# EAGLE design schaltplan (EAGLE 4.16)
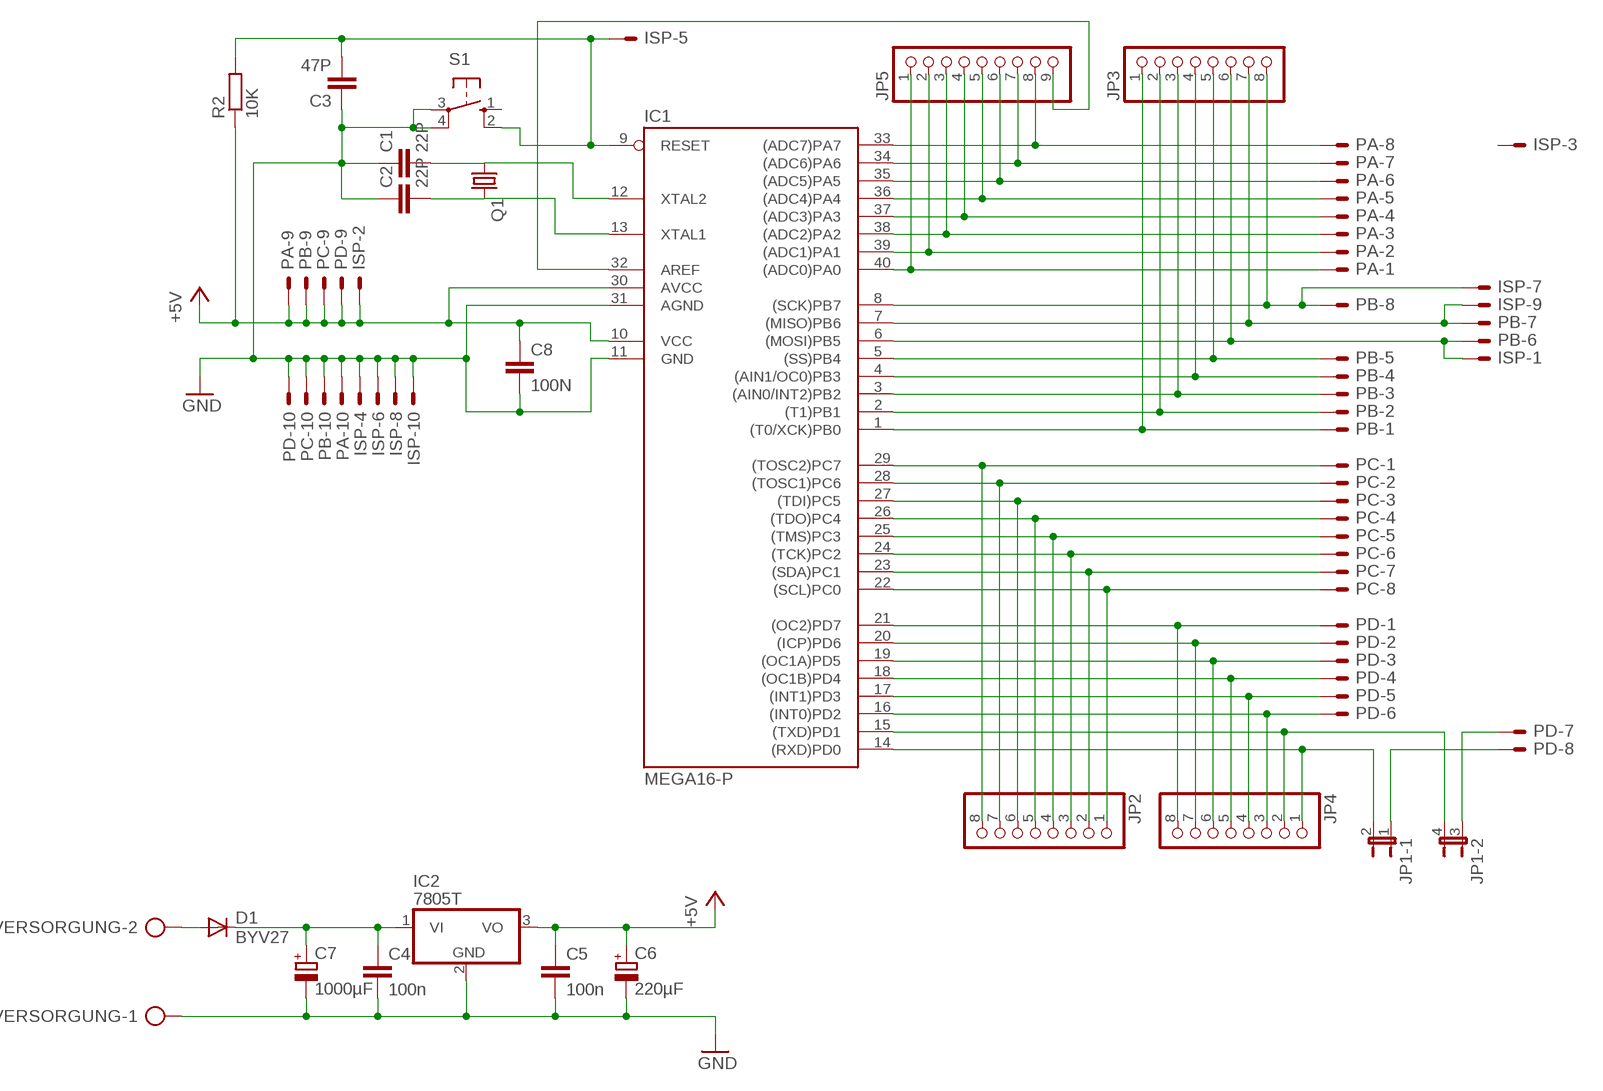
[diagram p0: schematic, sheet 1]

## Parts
C1  22P  C-EU025-024X044  [C025-024X044]
C2  22P  C-EU025-024X044  [C025-024X044]
C3  47P  C-EU025-024X044  [C025-024X044]
C4  100n  C-EU050-024X044  [C050-024X044]
C5  100n  C-EU050-024X044  [C050-024X044]
C6  220µF  CPOL-EUE5-10.5  [E5-10,5]
C7  1000µF  CPOL-EUE5-13  [E5-13]
C8  100N  C-EU050-024X044  [C050-024X044]
D1  BYV27  [SOD57-10]
IC1  MEGA16-P  [DIL40]
IC2  7805T  [TO220H]
ISP  ML10E  [ML10]
JP1  JP2QE  [JP2Q]
JP2  PINHD-1X8  [1X08]
JP3  PINHD-1X8  [1X08]
JP4  PINHD-1X8  [1X08]
JP5  PINHD-1X9  [1X09]
PA  ML10E  [ML10]
PB  ML10E  [ML10]
PC  ML10E  [ML10]
PD  ML10E  [ML10]
Q1  CRYSTALHC18U-V  [HC18U-V]
R2  10K  R-EU_0207/7  [0207/7]
S1  10-XX  [B3F-10XX]
VERSORGUNG  AK500/2  [AK500/2]

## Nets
+5V: C5.1 C6.+ C8.1 IC1.10(VCC) IC1.30(AVCC) IC2.3(VO) ISP.2 PA.9 PB.9 PC.9 PD.9 R2.1
GND: C1.1 C2.1 C3.1 C4.2 C5.2 C6.- C7.- C8.2 IC1.11(GND) IC1.31(AGND) IC2.2(GND) ISP.4 ISP.6 ISP.8 ISP.10 PA.10 PB.10 PC.10 PD.10 S1.3(P) S1.4(P1) VERSORGUNG.1
N$1: IC1.33((ADC7)PA7) JP5.8 PA.8
N$2: IC1.34((ADC6)PA6) JP5.7 PA.7
N$3: IC1.35((ADC5)PA5) JP5.6 PA.6
N$4: IC1.36((ADC4)PA4) JP5.5 PA.5
N$5: IC1.37((ADC3)PA3) JP5.4 PA.4
N$6: IC1.38((ADC2)PA2) JP5.3 PA.3
N$7: IC1.39((ADC1)PA1) JP5.2 PA.2
N$8: IC1.40((ADC0)PA0) JP5.1 PA.1
N$9: IC1.6((MOSI)PB5) ISP.1 JP3.6 PB.6
N$10: D1.A VERSORGUNG.2
N$12: JP1.1 PD.8
N$13: JP1.3 PD.7
N$14: C4.1 C7.+ D1.C IC2.1(VI)
N$15: IC1.2((T1)PB1) JP3.2 PB.2
N$16: IC1.1((T0/XCK)PB0) JP3.1 PB.1
N$17: IC1.29((TOSC2)PC7) JP2.8 PC.1
N$18: IC1.28((TOSC1)PC6) JP2.7 PC.2
N$19: IC1.27((TDI)PC5) JP2.6 PC.3
N$20: IC1.26((TDO)PC4) JP2.5 PC.4
N$21: IC1.25((TMS)PC3) JP2.4 PC.5
N$22: IC1.24((TCK)PC2) JP2.3 PC.6
N$23: IC1.23((SDA)PC1) JP2.2 PC.7
N$24: IC1.22((SCL)PC0) JP2.1 PC.8
N$25: IC1.21((OC2)PD7) JP4.8 PD.1
N$26: IC1.20((ICP)PD6) JP4.7 PD.2
N$27: IC1.19((OC1A)PD5) JP4.6 PD.3
N$28: IC1.18((OC1B)PD4) JP4.5 PD.4
N$29: IC1.17((INT1)PD3) JP4.4 PD.5
N$30: IC1.16((INT0)PD2) JP4.3 PD.6
N$31: IC1.15((TXD)PD1) JP1.4 JP4.2
N$32: IC1.14((RXD)PD0) JP1.2 JP4.1
N$33: C1.2 IC1.12(XTAL2) Q1.1
N$36: C2.2 IC1.13(XTAL1) Q1.2
N$37: C3.2 IC1.9(RESET) ISP.5 R2.2 S1.2(S1)
N$40: IC1.7((MISO)PB6) ISP.9 JP3.7 PB.7
N$41: IC1.8((SCK)PB7) ISP.7 JP3.8 PB.8
N$42: IC1.32(AREF) JP5.9
N$44: IC1.3((AIN0/INT2)PB2) JP3.3 PB.3
N$46: IC1.4((AIN1/OC0)PB3) JP3.4 PB.4
N$47: IC1.5((SS)PB4) JP3.5 PB.5
Unconnected: ISP.3 S1.1(S)

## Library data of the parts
C1-C5 C8 = rcl:C-EU: CAPACITOR, European symbol
C6 C7 = rcl:CPOL-EU: POLARIZED CAPACITOR, European symbol
D1 = diode:BYV27: DIODE
IC1 = atmel:MEGA16-P: MICROCONTROLLER 16 Kbytes FLASH 1 kbytes SRAM 512 bytes EEPROM USART 8-channel 10 bit ADC Source: avr.lbr
IC2 = linear:78*: Positive VOLTAGE REGULATOR Source: http://cache.national.com/ds/LM/LM78L05.pdf http://www.fairchildsemi.com/ds/LM/LM7805.pdf
ISP PA PB PC PD = con-harting-ml:ML10?E: HARTING
JP1 = jumper:JP2QE: JUMPER
JP2-JP4 = pinhead:PINHD-1X8: PIN HEADER
JP5 = pinhead:PINHD-1X9: PIN HEADER
Q1 = crystal:CRYSTAL: CRYSTAL
R2 = rcl:R-EU_: RESISTOR, European symbol
S1 = switch-omron:10-XX: OMRON SWITCH
VERSORGUNG = con-ptr500:AK500/2: CONNECTOR

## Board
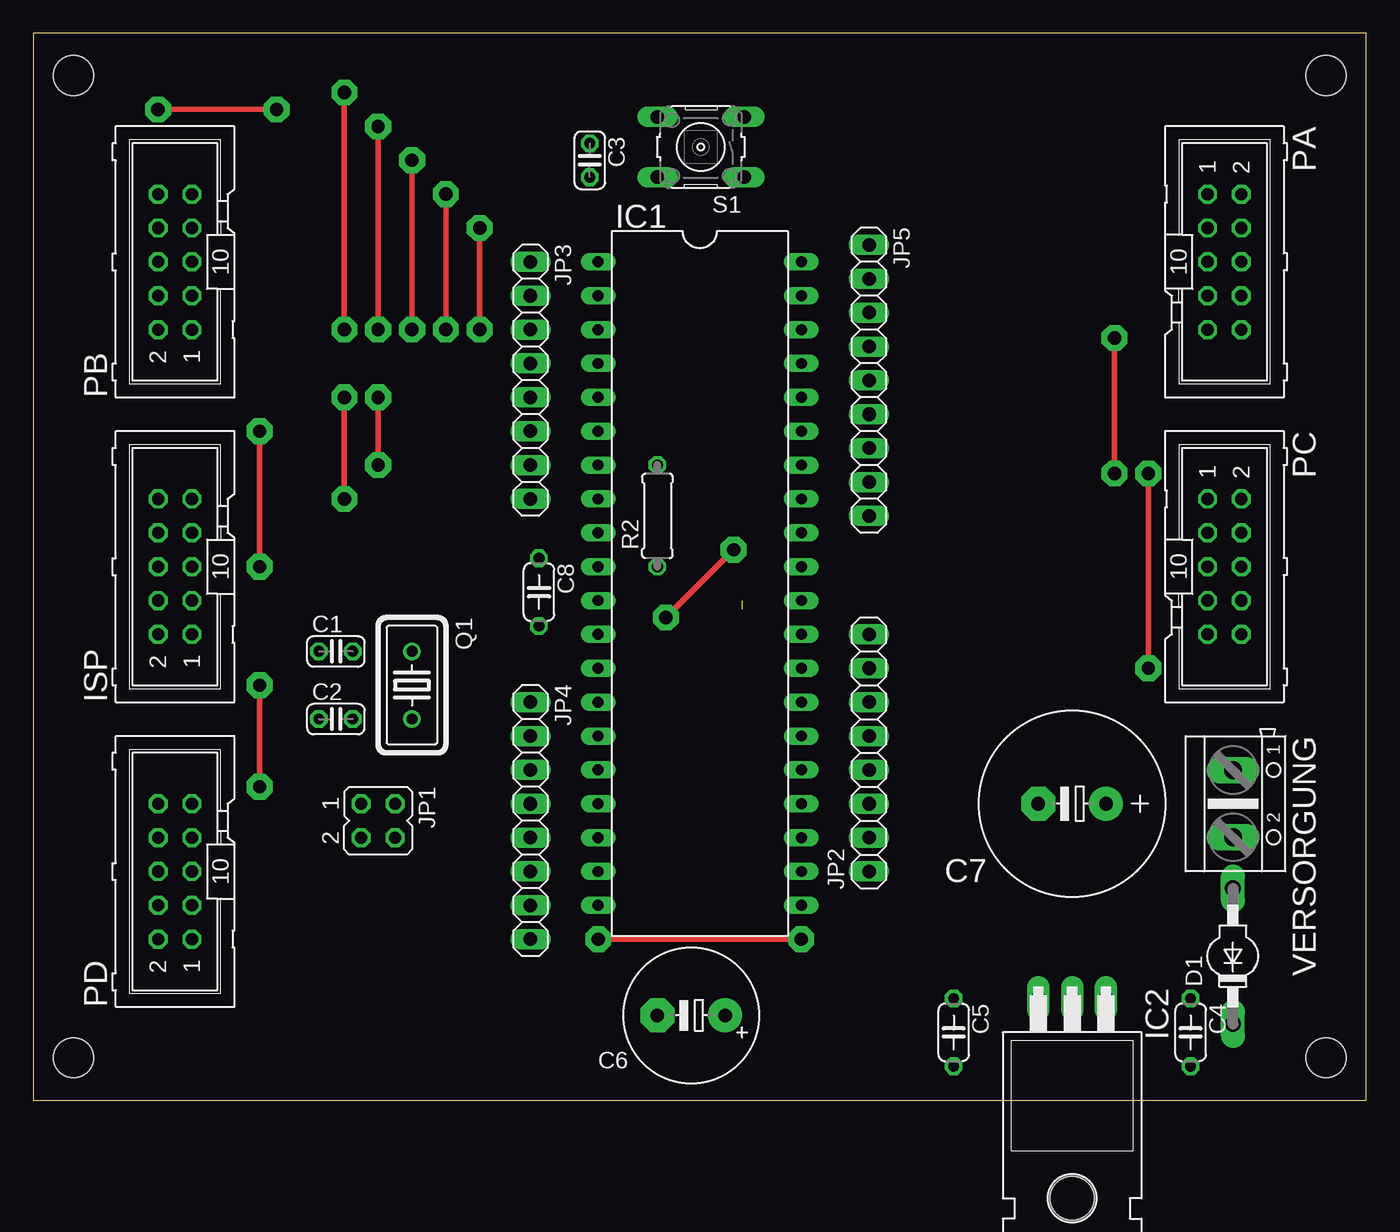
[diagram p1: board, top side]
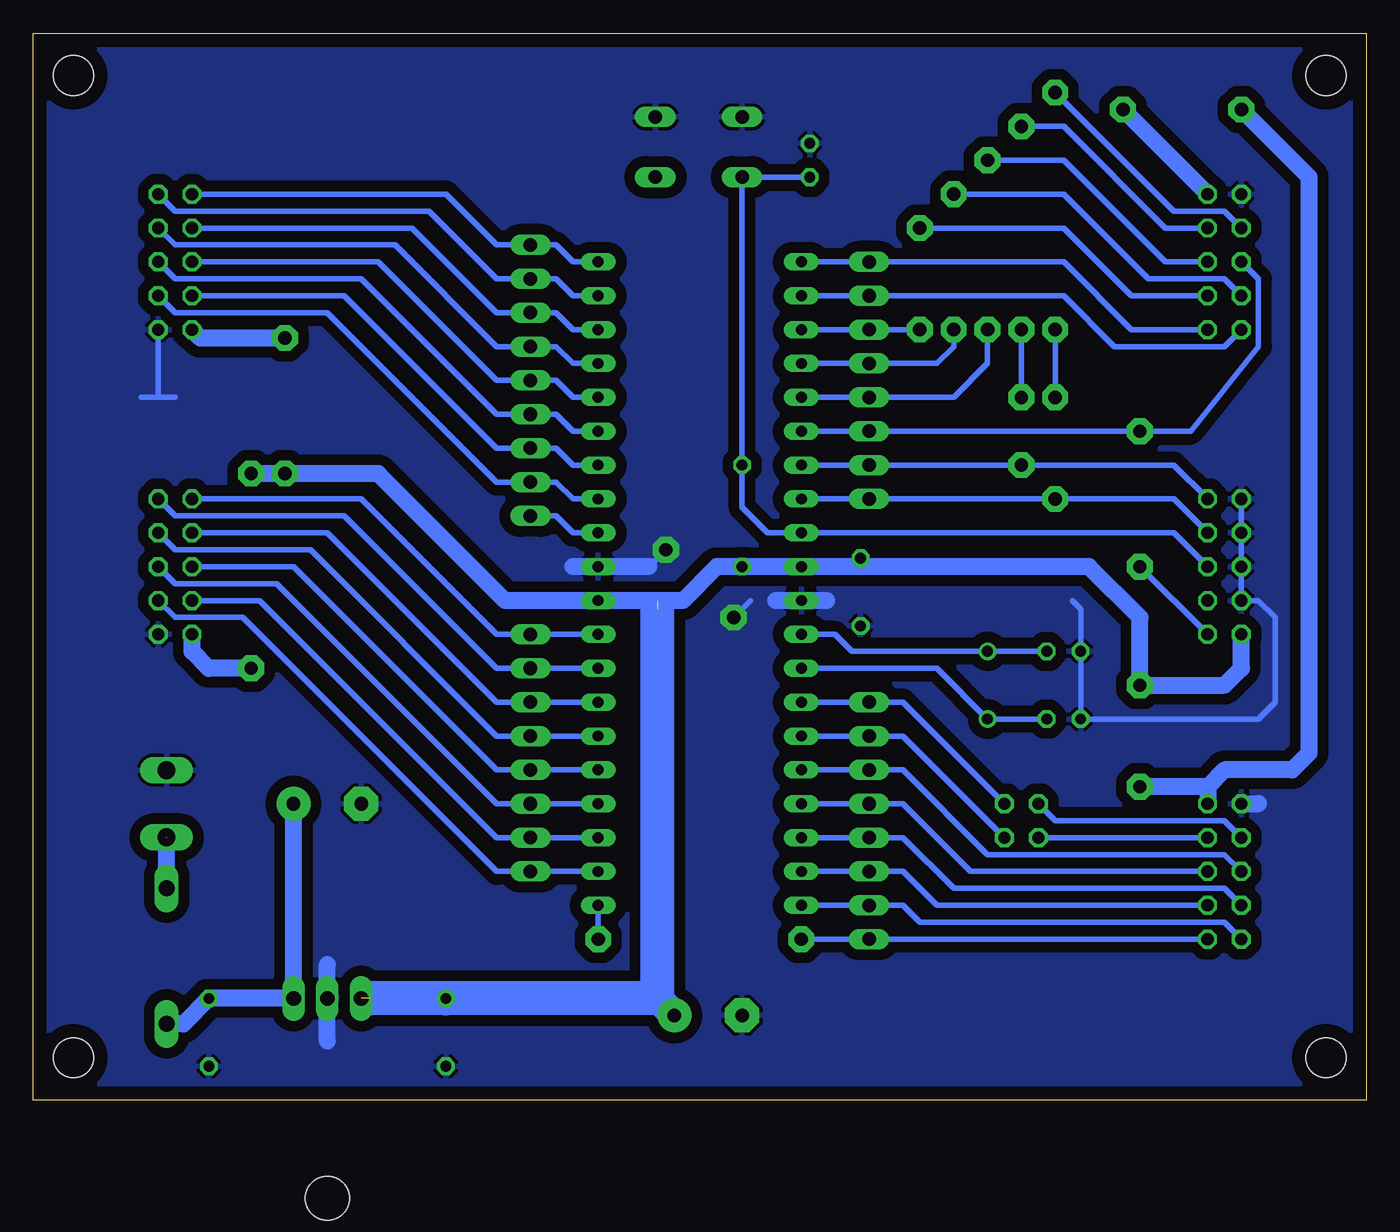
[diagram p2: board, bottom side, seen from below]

Size 100 x 80 mm. Coordinates in mm from the lower left corner, seen from the top.
Outline: 0,0 100,0 100,80 0,80 0,0
Copper layers (1*16): Top 0.035mm / dielectric 1.5mm / Bottom 0.035mm
Design rules "default": minimum track width 10mil, minimum drill 24mil, track to track 8mil, track to pad 8mil, pad to pad 8mil, via to via 8mil, smd to smd 8mil, copper to edge 40mil, drill to drill 8mil, minimum pad ring 10mil, minimum via ring 8mil, stop-mask expansion 4mil, vias tented up to drill 0mil, thermal gap 10mil
Holes 3 mm at 3.01,3.17 96.99,3.17 3.01,76.83 96.99,76.83

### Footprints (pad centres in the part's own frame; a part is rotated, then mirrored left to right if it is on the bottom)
C025-024X044 = drill 0.813 octagon: 1 -1.27,0; 2 1.27,0
C050-024X044 = drill 0.813 octagon: 1 -2.54,0; 2 2.54,0
E5-10,5 = drill 1.016 pad 2.54 round: + -2.54,0 | drill 1.016 pad 2.54 octagon: - 2.54,0
E5-13 = drill 1.016 pad 2.54 round: + -2.54,0 | drill 1.016 pad 2.54 octagon: - 2.54,0
SOD57-10 = drill 1.194 long: A 5.08,0; C -5.08,0
DIL40 = drill 0.813 long: 1 -24.13,-7.62; 2 -21.59,-7.62; 3 -19.05,-7.62; 4 -16.51,-7.62; 5 -13.97,-7.62; 6 -11.43,-7.62; 7 -8.89,-7.62; 8 -6.35,-7.62; 9 -3.81,-7.62; 10 -1.27,-7.62; 11 1.27,-7.62; 12 3.81,-7.62; 13 6.35,-7.62; 14 8.89,-7.62; 15 11.43,-7.62; 16 13.97,-7.62; 17 16.51,-7.62; 18 19.05,-7.62; 19 21.59,-7.62; 20 24.13,-7.62; 21 24.13,7.62; 22 21.59,7.62; 23 19.05,7.62; 24 16.51,7.62; 25 13.97,7.62; 26 11.43,7.62; 27 8.89,7.62; 28 6.35,7.62; 29 3.81,7.62; 30 1.27,7.62; 31 -1.27,7.62; 32 -3.81,7.62; 33 -6.35,7.62; 34 -8.89,7.62; 35 -11.43,7.62; 36 -13.97,7.62; 37 -16.51,7.62; 38 -19.05,7.62; 39 -21.59,7.62; 40 -24.13,7.62
TO220H = drill 1.118 long: 1 -2.54,-10.16; 2 0,-10.16; 3 2.54,-10.16 | hole 3.302: 0,4.826
ML10 = drill 0.914 octagon: 1 -5.08,-1.27; 2 -5.08,1.27; 3 -2.54,-1.27; 4 -2.54,1.27; 5 0,-1.27; 6 0,1.27; 7 2.54,-1.27; 8 2.54,1.27; 9 5.08,-1.27; 10 5.08,1.27
JP2Q = drill 0.914 octagon: 1 -1.27,-1.27; 2 -1.27,1.27; 3 1.27,-1.27; 4 1.27,1.27
1X08 = drill 1.016 long: 1 -8.89,0; 2 -6.35,0; 3 -3.81,0; 4 -1.27,0; 5 1.27,0; 6 3.81,0; 7 6.35,0; 8 8.89,0
1X09 = drill 1.016 long: 1 -10.16,0; 2 -7.62,0; 3 -5.08,0; 4 -2.54,0; 5 0,0; 6 2.54,0; 7 5.08,0; 8 7.62,0; 9 10.16,0
HC18U-V = drill 0.813 round: 1 -2.54,0; 2 2.54,0
0207/7 = drill 0.813 octagon: 1 -3.81,0; 2 3.81,0
B3F-10XX = drill 1.016 long: 1 -3.251,2.261; 2 3.251,2.261; 3 -3.251,-2.261; 4 3.251,-2.261
AK500/2 = drill 1.321 long: 1 -2.515,0; 2 2.515,0

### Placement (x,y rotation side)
C1  22.7,33.65 0 top
C2  22.7,28.57 0 top
C3  41.74,70.48 270 top
C4  86.83,5.08 270 top
C5  69.05,5.08 270 top
C6  49.37,6.34 180 top
C7  77.94,22.22 180 top
C8  37.94,38.1 270 top
D1  90,10.79 90 top
IC1  50,38.73 270 top
IC2  77.94,-2.54 180 top
ISP  10.63,40 90 top
JP1  25.87,20.95 270 top
JP2  62.7,26.03 90 top
JP3  37.3,53.97 270 top
JP4  37.3,20.95 270 top
JP5  62.7,53.97 270 top
PA  89.37,62.86 270 top
PB  10.63,62.86 90 top
PC  89.37,40 270 top
PD  10.63,17.14 90 top
Q1  28.41,31.11 270 top
R2  46.82,43.81 90 top
S1  50.08,71.47 180 top
VERSORGUNG  90,22.22 270 top

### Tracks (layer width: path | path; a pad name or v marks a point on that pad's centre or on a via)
+5V  (via drill 1 pad 1.93)  (2 unrouted)
  Top 0.406: v16.98,23.49 v16.98,31.11 | v9.36,74.29 v18.25,74.29 | v81.11,46.98 v81.11,57.15 | v83.66,46.98 v83.66,32.38
  Bottom 1.27: ISP.2 9.36,32.38 10.63,31.11 v16.98,31.11 16.98,36.19 20.79,40 37.94,40 | 11.9,23.49 PD.9 | 11.9,23.49 v16.98,23.49 | 11.9,23.49 10.63,24.76 5.55,24.76 4.28,26.03 4.28,69.21 v9.36,74.29 | v18.25,74.29 PB.9 | v83.66,46.98 v81.11,46.98 74.13,46.98 64.61,37.46 IC1.30 53.17,37.46 51.27,37.46 48.73,40 R2.1 IC1.10 37.94,40 | v83.66,32.38 86.83,32.38 88.1,33.65 PC.9 | v81.11,57.15 87.47,57.15 PA.9 | 37.94,40 C8.1
  Bottom 2.184: C6.+ 53.17,7.62
  Bottom 2.54: 74.77,7.62 C5.1 53.17,7.62 53.17,36.83
GND  (via drill 1 pad 1.93)
  Top 0.406: v47.46,36.19 v52.54,41.27
  Bottom 0.406: 22.06,37.46 21.42,36.83 C2.1 8.09,28.57 6.82,29.84 6.82,36.19 8.09,37.46 ISP.4 ISP.10 | v47.46,36.19 46.19,37.46 | v52.54,41.27 53.81,40 | 90.64,52.7 89.37,52.7 | 90.64,52.7 PA.10 | 90.64,52.7 91.91,52.7
  Bottom 1.27: 53.81,40 IC1.31 59.52,40 | PD.10 8.09,22.22 | 77.94,10.16 IC2.2 77.94,4.44 | 44.28,37.46 IC1.11 40.48,37.46
  pour Bottom (isolate 0.813): 0.47,0.63 0.47,79.37 99.53,79.37 99.53,0.63
N$1
  Bottom 0.406: IC1.33 59.52,45.08 60.8,46.35 JP5.8 65.24,46.35 77.94,59.05 89.37,59.05 PA.8
N$2
  Bottom 0.406: IC1.34 59.52,47.62 60.8,48.89 JP5.7 65.24,48.89 76.67,60.32 PA.7
N$3
  Bottom 0.406: IC1.35 59.52,50.16 60.8,51.43 JP5.6 65.24,51.43 75.4,61.59 89.37,61.59 PA.6
N$4
  Bottom 0.406: IC1.36 59.52,52.7 60.8,53.97 JP5.5 65.24,53.97 74.13,62.86 PA.5
N$5
  Bottom 0.406: IC1.37 59.52,55.24 60.8,56.51 JP5.4 65.24,56.51 72.86,64.13 89.37,64.13 PA.4
N$6
  Bottom 0.406: IC1.38 59.52,57.78 60.8,59.05 JP5.3 65.24,59.05 71.59,65.4 PA.3
N$7
  Bottom 0.406: IC1.39 59.52,60.32 60.8,61.59 JP5.2 65.24,61.59 70.32,66.67 89.37,66.67 PA.2
N$8
  Bottom 0.406: IC1.40 59.52,62.86 60.8,64.13 JP5.1 65.24,64.13 69.05,67.94 PA.1
N$9  (via drill 1 pad 1.93)
  Top 0.406: v16.98,40 v16.98,50.16
  Bottom 0.406: ISP.1 v16.98,40 | PB.6 8.09,61.59 8.09,56.51 13.17,50.16 v16.98,50.16 JP3.6 IC1.6
N$10  (1 unrouted)
  Bottom 1.27: D1.A 90,19.68
N$12
  Bottom 0.406: JP1.1 23.33,20.95 10.63,20.95 PD.8
N$13
  Bottom 0.406: PD.7 JP1.3
N$14
  Bottom 1.27: C7.+ IC2.1 C4.1 88.73,5.71 D1.C
N$15
  Bottom 0.406: PB.2 10.63,56.51 18.88,56.51 22.7,60.32 JP3.2 IC1.2
N$16
  Bottom 0.406: PB.1 17.61,57.78 22.7,62.86 JP3.1 IC1.1
N$17
  Bottom 0.406: IC1.29 JP2.8 65.24,34.92 75.4,45.08 PC.1
N$18
  Bottom 0.406: IC1.28 JP2.7 65.24,32.38 76.67,43.81 89.37,43.81 PC.2
N$19
  Bottom 0.406: IC1.27 JP2.6 65.24,29.84 77.94,42.54 PC.3
N$20
  Bottom 0.406: IC1.26 JP2.5 65.24,27.3 79.21,41.27 89.37,41.27 PC.4
N$21
  Bottom 0.406: IC1.25 JP2.4 65.24,24.76 80.48,40 PC.5
N$22
  Bottom 0.406: IC1.24 JP2.3 65.24,22.22 81.75,38.73 89.37,38.73 PC.6
N$23
  Bottom 0.406: IC1.23 JP2.2 65.24,19.68 83.02,37.46 PC.7
N$24
  Bottom 0.406: IC1.22 JP2.1 65.24,17.14 84.29,36.19 89.37,36.19 PC.8
N$25  (via drill 1 pad 1.93)
  Top 0.406: v42.38,12.06 v57.62,12.06
  Bottom 0.406: PD.1 JP4.8 v42.38,12.06 43.02,12.06 | v57.62,12.06 IC1.21
N$26
  Bottom 0.406: IC1.20 JP4.7 34.76,14.6 33.49,13.33 10.63,13.33 PD.2
N$27
  Bottom 0.406: IC1.19 JP4.6 34.76,17.14 32.22,14.6 PD.3
N$28
  Bottom 0.406: IC1.18 JP4.5 34.76,19.68 30.95,15.87 10.63,15.87 PD.4
N$29
  Bottom 0.406: IC1.17 JP4.4 34.76,22.22 29.68,17.14 PD.5
N$30
  Bottom 0.406: IC1.16 JP4.3 34.76,24.76 28.41,18.41 10.63,18.41 PD.6
N$31
  Bottom 0.406: JP1.4 34.76,27.3 JP4.2 IC1.15
N$32
  Bottom 0.406: JP1.2 34.76,29.84 JP4.1 IC1.14
N$33
  Bottom 0.406: IC1.12 39.84,34.92 38.57,33.65 Q1.1 C1.2
N$36
  Bottom 0.406: C2.2 Q1.2 32.22,32.38 IC1.13
N$37  (1 unrouted)
  Bottom 0.406: ISP.5 14.44,42.54 IC1.9 44.92,42.54 46.82,44.45 R2.2 S1.2 C3.2
N$40  (via drill 1 pad 1.93)
  Top 0.406: v25.87,57.78 v25.87,73.02 | v25.87,47.62 v25.87,52.7
  Bottom 0.406: v25.87,73.02 22.7,73.02 15.08,65.4 PB.7 | ISP.9 14.44,47.62 v25.87,47.62 JP3.7 IC1.7 | v25.87,52.7 v25.87,57.78
N$41  (via drill 1 pad 1.93)
  Top 0.406: v23.33,57.78 v23.33,75.56 | v23.33,45.08 v23.33,52.7
  Bottom 0.406: v23.33,75.56 14.44,66.67 10.63,66.67 PB.8 | ISP.7 14.44,45.08 v23.33,45.08 JP3.8 IC1.8 | v23.33,52.7 v23.33,57.78
N$42
  Bottom 0.406: IC1.32 59.52,42.54 60.8,43.81 JP5.9
N$44  (via drill 1 pad 1.93)
  Top 0.406: v33.49,65.4 v33.49,57.78
  Bottom 0.406: v33.49,65.4 22.7,65.4 17.61,60.32 PB.3 | IC1.3 JP3.3 v33.49,57.78
N$46  (via drill 1 pad 1.93)
  Top 0.406: v30.95,67.94 v30.95,57.78
  Bottom 0.406: v30.95,67.94 22.7,67.94 16.34,61.59 10.63,61.59 PB.4 | v30.95,57.78 30.95,56.51 32.22,55.24 JP3.4 IC1.4
N$47  (via drill 1 pad 1.93)
  Top 0.406: v28.41,70.48 v28.41,57.78
  Bottom 0.406: v28.41,70.48 22.7,70.48 15.08,62.86 PB.5 | v28.41,57.78 28.41,55.24 30.95,52.7 JP3.5 IC1.5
